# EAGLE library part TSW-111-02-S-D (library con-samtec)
THROUGH-HOLE .025" SQ POST HEADER Source: Samtec TSW.pdf
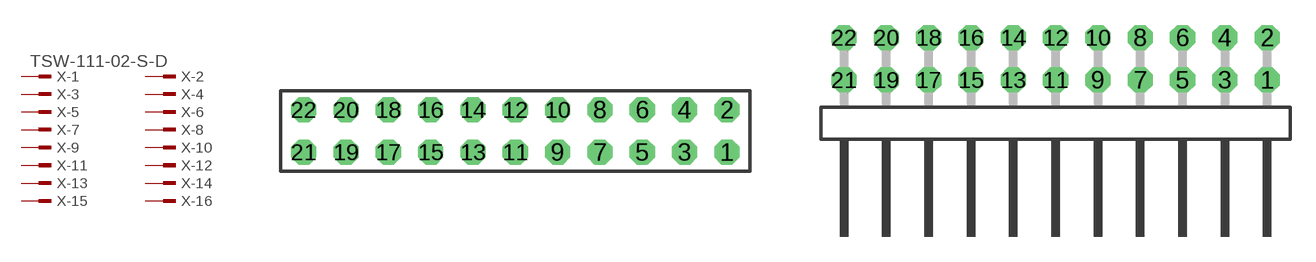
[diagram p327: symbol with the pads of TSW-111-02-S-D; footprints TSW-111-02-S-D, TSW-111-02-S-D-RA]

Designator prefix X; gates -1=MPINV -2=MPIN -3=MPIN -4=MPIN -5=MPIN -6=MPIN -7=MPIN -8=MPIN -9=MPIN -10=MPIN -11=MPIN -12=MPIN -13=MPIN -14=MPIN -15=MPIN -16=MPIN -17=MPIN -18=MPIN -19=MPIN -20=MPIN -21=MPIN -22=MPIN

## TSW-111-02-S-D (OC_FARNELL: unknown; OC_NEWARK: unknown)  [TSW-111-02-S-D]
1  -1:1  pas
2  -2:1  pas
3  -3:1  pas
4  -4:1  pas
5  -5:1  pas
6  -6:1  pas
7  -7:1  pas
8  -8:1  pas
9  -9:1  pas
10  -10:1  pas
11  -11:1  pas
12  -12:1  pas
13  -13:1  pas
14  -14:1  pas
15  -15:1  pas
16  -16:1  pas
17  -17:1  pas
18  -18:1  pas
19  -19:1  pas
20  -20:1  pas
21  -21:1  pas
22  -22:1  pas

## TSW-111-02-S-D-RA (OC_FARNELL: unknown; OC_NEWARK: unknown)  [TSW-111-02-S-D-RA]
Pads as for TSW-111-02-S-D

## Footprint TSW-111-02-S-D (pad centres in mm)
THROUGH-HOLE .025" SQ POST HEADER Source: Samtec TSW.pdf
drill 1 pad 1.5 octagon: 1 12.7,-1.27; 2 12.7,1.27; 3 10.16,-1.27; 4 10.16,1.27; 5 7.62,-1.27; 6 7.62,1.27; 7 5.08,-1.27; 8 5.08,1.27; 9 2.54,-1.27; 10 2.54,1.27; 11 0,-1.27; 12 0,1.27; 13 -2.54,-1.27; 14 -2.54,1.27; 15 -5.08,-1.27; 16 -5.08,1.27; 17 -7.62,-1.27; 18 -7.62,1.27; 19 -10.16,-1.27; 20 -10.16,1.27; 21 -12.7,-1.27; 22 -12.7,1.27

## Footprint TSW-111-02-S-D-RA (pad centres in mm)
THROUGH-HOLE .025" SQ POST HEADER Source: Samtec TSW.pdf
drill 1 pad 1.5 octagon: 1 12.7,1.524; 2 12.7,4.064; 3 10.16,1.524; 4 10.16,4.064; 5 7.62,1.524; 6 7.62,4.064; 7 5.08,1.524; 8 5.08,4.064; 9 2.54,1.524; 10 2.54,4.064; 11 0,1.524; 12 0,4.064; 13 -2.54,1.524; 14 -2.54,4.064; 15 -5.08,1.524; 16 -5.08,4.064; 17 -7.62,1.524; 18 -7.62,4.064; 19 -10.16,1.524; 20 -10.16,4.064; 21 -12.7,1.524; 22 -12.7,4.064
